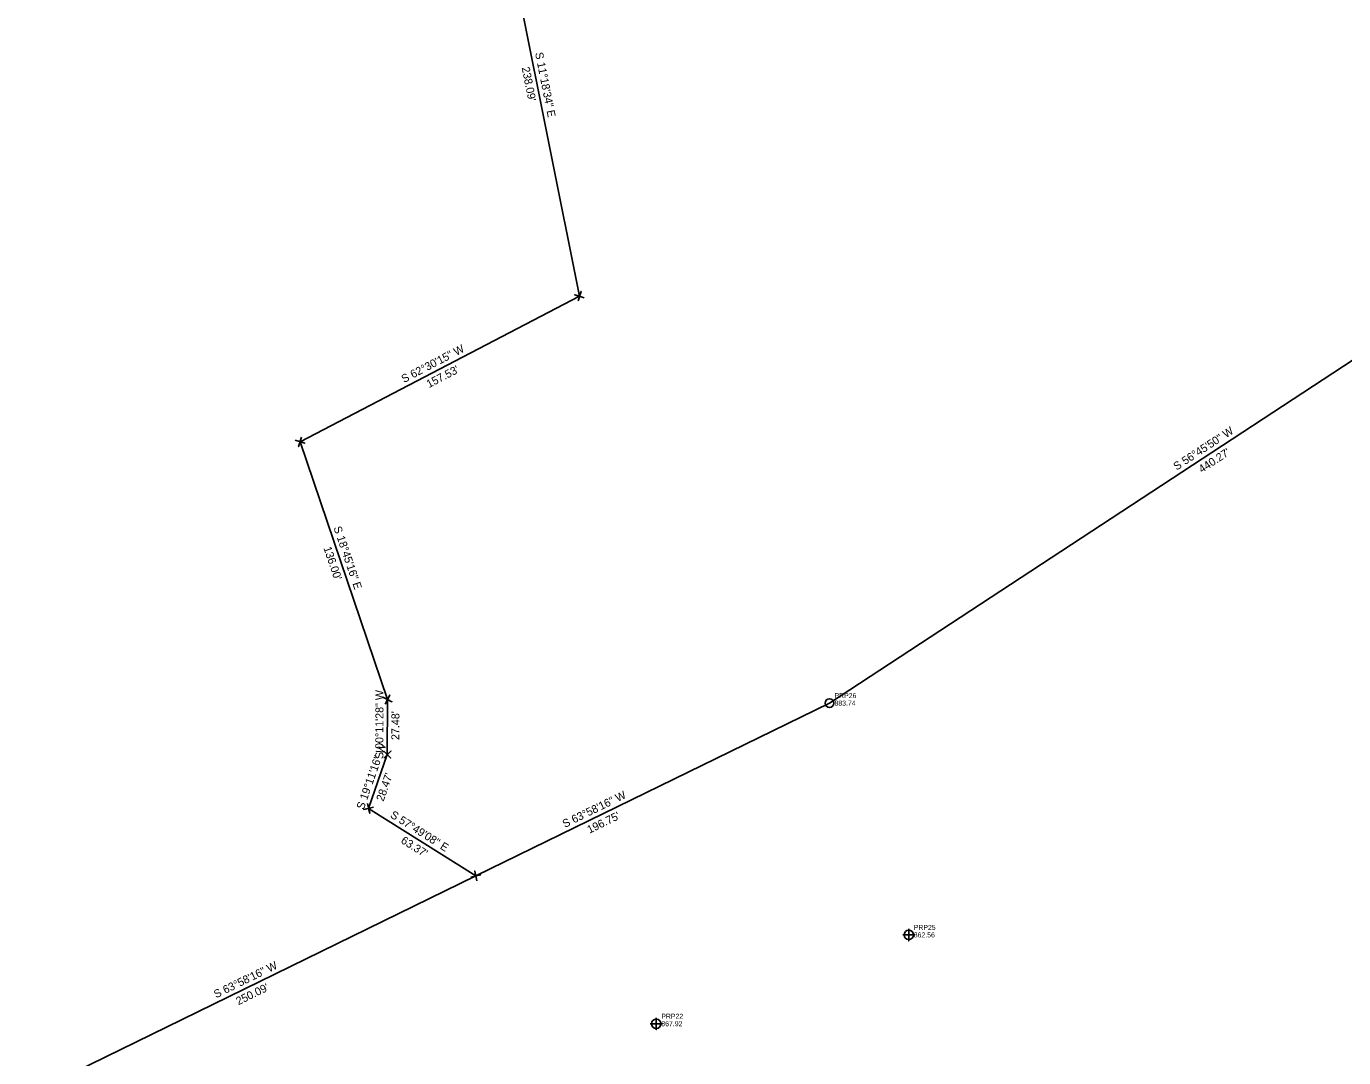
# Model space of a CAD drawing. Extents: x 1316460 to 1321645, y 684173 to 687077.
# Drawn here: x 1317809 to 1318467, y 685124 to 685639 of the extents above; entities that cross this region are included whole.
import ezdxf

# ---------------------------------------------------------------- set-up
doc = ezdxf.new("R2010")
doc.units = 0
for name, color, linetype in [('CTL Supplemental Horizontal and Vertical CELL', 7, 'Continuous'), ('CTL Supplemental Horizontal and Vertical Cogo Number', 7, 'Continuous'), ('Exist Earthen Structure Embankment Shoulder Cogo Description', 7, 'Continuous'), ('Exist Hydrographic Confluence CELL', 7, 'Continuous'), ('Exist Hydrographic Confluence Cogo Elevation', 7, 'Continuous'), ('Exist Hydrographic Confluence Cogo Number', 7, 'Continuous'), ('Exist Property Corner CELL', 7, 'Continuous'), ('Exist Property Line', 7, 'Continuous'), ('Exist Property Line Text', 7, 'Continuous')]:
    doc.layers.add(name, color=color, linetype=linetype)

msp = doc.modelspace()

# ---------------------------------------------------------------- linework, layer by layer
at = {"layer": 'Exist Earthen Structure Embankment Shoulder Cogo Description'}
for points in [[(1318249.8, 685188.53), (1318249.8, 685182.53), (1318249.8, 685185.53), (1318252.8, 685185.53), (1318246.8, 685185.53)], [(1318123.59, 685144.16), (1318123.59, 685138.16), (1318123.59, 685141.16), (1318126.59, 685141.16), (1318120.59, 685141.16)]]:
    msp.add_lwpolyline(points, dxfattribs=at)
for centre in [(1318249.8, 685185.53), (1318123.59, 685141.16)]:
    msp.add_circle(centre, 2.34, dxfattribs=at)
at = {"layer": 'Exist Hydrographic Confluence CELL'}
for radius in [2.2, 2.2, 0.0707, 0.0707]:
    msp.add_circle((1318210.18, 685301.35), radius, dxfattribs=at)
at = {"layer": 'Exist Property Corner CELL'}
for p, q in [((1318085.2, 685504.64), (1318085.2, 685504.64)), ((1317945.47, 685431.91), (1317945.47, 685431.91)), ((1317989.19, 685303.13), (1317989.19, 685303.13)), ((1317989.1, 685275.65), (1317989.1, 685275.65)), ((1317979.75, 685248.76), (1317979.75, 685248.76)), ((1318033.38, 685215.01), (1318033.38, 685215.01))]:
    msp.add_line(p, q, dxfattribs=at)
for points in [[(1318084.45, 685502.25), (1318085.96, 685507.02), (1318085.2, 685504.64), (1318082.82, 685505.39), (1318087.59, 685503.89)], [(1317946.22, 685434.29), (1317944.72, 685429.52), (1317945.47, 685431.91), (1317947.85, 685431.16), (1317943.08, 685432.66)], [(1317986.95, 685304.24), (1317991.44, 685302.02), (1317989.19, 685303.13), (1317990.3, 685305.37), (1317988.09, 685300.89)], [(1317987.34, 685277.42), (1317990.86, 685273.88), (1317989.1, 685275.65), (1317990.88, 685277.41), (1317987.33, 685273.89)], [(1317982.18, 685249.32), (1317977.31, 685248.21), (1317979.75, 685248.76), (1317980.3, 685246.32), (1317979.19, 685251.2)], [(1318030.95, 685214.45), (1318035.82, 685215.56), (1318033.38, 685215.01), (1318032.83, 685217.45), (1318033.94, 685212.57)]]:
    msp.add_lwpolyline(points, dxfattribs=at)
at = {"layer": 'Exist Property Line'}
for p, q in [((1318038.51, 685738.1), (1318085.2, 685504.64)), ((1318578.43, 685542.66), (1318210.18, 685301.35)), ((1318085.2, 685504.64), (1317945.47, 685431.91)), ((1317945.47, 685431.91), (1317989.19, 685303.13)), ((1317989.19, 685303.13), (1317989.1, 685275.65)), ((1318210.18, 685301.35), (1318033.38, 685215.01)), ((1317989.1, 685275.65), (1317979.75, 685248.76)), ((1317979.75, 685248.76), (1318033.38, 685215.01)), ((1318033.38, 685215.01), (1317808.66, 685105.26))]:
    msp.add_line(p, q, dxfattribs=at)

# ---------------------------------------------------------------- texts
at = {"layer": 'CTL Supplemental Horizontal and Vertical CELL'}
for s, p in [('PRP25', (1318252.3, 685188.03)), ('PRP22', (1318126.09, 685143.66))]:
    msp.add_text(s, height=2.5, dxfattribs=at).set_placement(p)
at = {"layer": 'CTL Supplemental Horizontal and Vertical Cogo Number'}
for s, p in [('862.56', (1318252.3, 685184.28)), ('867.92', (1318126.09, 685139.91))]:
    msp.add_text(s, height=2.5, dxfattribs=at).set_placement(p)
at = {"layer": 'Exist Hydrographic Confluence Cogo Elevation'}
msp.add_text('883.74', height=2.5, dxfattribs=at).set_placement((1318212.68, 685300.1))
msp.add_text('883.74', height=2.5, dxfattribs=at).set_placement((1318212.68, 685300.1))
at = {"layer": 'Exist Hydrographic Confluence Cogo Number'}
msp.add_text('PRP26', height=2.5, dxfattribs=at).set_placement((1318212.68, 685303.85))
msp.add_text('PRP26', height=2.5, dxfattribs=at).set_placement((1318212.68, 685303.85))
at = {"layer": 'Exist Property Line Text'}
for s, rotation, p in [('S 11%%D18\'34" E', 281.30944, (1318062.95, 685626.12)), ("238.09'", 281.30944, (1318056.26, 685618.79)), ('S 62%%D30\'15" W', 27.49583, (1317997.43, 685461.21)), ("157.53'", 27.49583, (1318009.95, 685458.7)), ('S 56%%D45\'50" W', 33.23608, (1318383.73, 685417.46)), ("440.27'", 33.23608, (1318396.31, 685416.14)), ('S 18%%D45\'16" E', 288.75444, (1317962.16, 685388.98)), ("136.00'", 288.75444, (1317957.15, 685378.85)), ('S 00%%D11\'28" W', 89.80889, (1317987.09, 685273.37)), ("27.48'", 89.80889, (1317995.13, 685282.89)), ('S 19%%D11\'16" W', 70.81222, (1317977.33, 685247.89)), ("28.47'", 70.81222, (1317987.2, 685251.93)), ('S 63%%D58\'16" W', 26.02887, (1318077.86, 685238.96)), ('S 57%%D49\'08" E', 327.81889, (1317990.22, 685244.53)), ("196.75'", 26.02887, (1318090.17, 685236.06)), ("63.37'", 327.81889, (1317995.52, 685231.75)), ('S 63%%D58\'16" W', 26.02887, (1317903.56, 685153.83)), ("250.09'", 26.02887, (1317914.65, 685150.35))]:
    msp.add_text(s, height=4, rotation=rotation, dxfattribs=at).set_placement(p)

doc.saveas('drawing.dxf')
